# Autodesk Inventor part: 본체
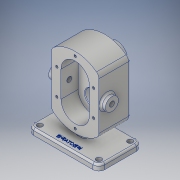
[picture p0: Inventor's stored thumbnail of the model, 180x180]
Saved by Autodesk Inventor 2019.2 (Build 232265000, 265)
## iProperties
Created: 2019-03
Part Number: 본체
Material: 알루미늄 6061
Document SubType Name: Modeling
Designer: User
Mass: 1187.16 g
Surface Area: 719.273 cm^2
Volume: 439.69 cm^3
Density: 2.7 g/cm^3
Appearance: 알루미늄 - 평지
Author: User
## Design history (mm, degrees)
sketch "스케치1"
  geometry: L1 (60, 73)-(-60, 73); L2 (-60, 73)-(-60, 0); L3 (-60, 0)-(60, 0); L4 (60, 0)-(60, 73); L5 (60, 73)-(-60, 0); L6 (-60, 73)-(60, 0); L7 (84, 0)-(-84, 0) reference; L8 (0, -14.6)-(0, 87.6) reference; 2 further points
  constraints: 12 end point, 3 midpoint, 2 parallel, 1 collinear, 1 horizontal, 1 perpendicular
  dimensions: "d0" = 73 distance between parallel lines of L3 L1; "d1" = 120 distance between parallel lines of L2 L4
extrude "돌출1" new body sketch "스케치1" distance "d2" = 10; taper "d3" = 0 deg
sketch "스케치2"
  geometry: L1 (0, -2)-(0, 12) reference; L2 (-40, 122.721)-(-40, 33.279); L3 (40, 122.721)-(40, 33.279); L4 (-40, 78)-(40, 78); L5 (-60, 0)-(60, 0) reference; L6 (-43.067, 138)-(65.49, 138); A1 r 60 centre (0, 78) between (40, 122.721) and (-40, 122.721); A2 r 60 centre (0, 78) between (-40, 33.279) and (40, 33.279); 1 further point
  constraints: 8 end point, 4 point on circle, 2 centre point, 2 midpoint, 2 point on line, 2 vertical, 1 horizontal, 1 tangent, 1 other
  dimensions: "d4" = 60 radius of A1; "d5" = 60 radius of A2; "d6" = 80 distance between parallel lines of L3 L2; "d7" = 78 distance between parallel lines of L5 L4; "d8" = 138 distance between parallel lines of L5 L6
extrude "돌출2" join sketch "스케치2" distance "d9" = 53; taper "d10" = 0 deg
sketch "스케치3"
  geometry: L1 (30, 43)-(0, 43); L2 (0, 43)-(0, 0); L3 (0, 0)-(30, 0); L4 (30, 0)-(30, 43); L5 (0, 0)-(10, 0) reference; L6 (0, 0)-(0, 73) reference
  constraints: 8 end point, 2 collinear, 2 parallel, 1 horizontal, 1 perpendicular
  dimensions: "d11" = 43 distance between parallel lines of L3 L1; "d12" = 30 distance between parallel lines of L6 L4
extrude "돌출3" join sketch "스케치3" stored distance "d13" = 12; taper "d14" = 0 deg
sketch "스케치4"
  geometry: L1 (-73, -33.279)-(0, -33.279) reference; L2 (-53, 0)-(-53, 89.443) reference; C1 r 11 at (-39, 44.721)
  constraints: 1 centre point
  dimensions: "d15" = 22 diameter of C1; "d16" = 78 distance from line of L1 C1.centre; "d17" = 14 distance from line of L2 C1.centre
extrude "돌출4" join sketch "스케치4" distance "d18" = 8; taper "d19" = 0 deg
fillet "모깎기1" dims "d20" = 3
sketch "스케치5"
  geometry: L1 (0, 56)-(0, 100); L2 (24, 56)-(24, 100); L3 (-24, 100)-(-24, 56); L4 (-60, 0)-(60, 0) reference; L5 (0, -27.6)-(0, 165.6) reference; A1 r 24 centre (0, 56) between (-24, 56) and (24, 56); A2 r 24 centre (0, 100) between (24, 100) and (-24, 100); 2 further points
  constraints: 8 end point, 4 point on circle, 4 tangent, 2 centre point, 1 collinear, 1 midpoint, 1 parallel, 1 vertical
  dimensions: "d21" = 24 radius of A2; "d22" = 44 distance of L1.start L1.end; "d23" = 78 distance from line of L4 point (0, 78)
extrude "돌출5" cut sketch "스케치5" distance "d24" = 29; taper "d25" = 0 deg
sketch "스케치6"
  geometry: C1 r 11 at (0, 0) reference; 2 further points
  constraints: 1 coincident
hole "구멍1" sketch "스케치6" at (0, 0) diameter "d26" = 8.376; stored, may be unused: countersink angle "d30" = 90 deg, drill point angle "d32" = 0 deg; dims "d27" = 20, "d28" = 4, "d29" = 2, "d31" = 8
fillet "모깎기2" dims "d33" = 3
sketch "스케치7"
  geometry: C1 r 11 at (0, 0) reference; 2 further points
  constraints: 1 coincident
hole "구멍2" sketch "스케치7" at (0, 0) diameter "d34" = 8.376; stored, may be unused: countersink angle "d38" = 90 deg, drill point angle "d40" = 0 deg; dims "d35" = 20, "d36" = 4, "d37" = 2, "d39" = 8
sketch "스케치8"
  geometry: C1 r 19 at (60, 100); A1 r 24 centre (60, 100) between (84, 100) and (36, 100) reference; 1 further point
  constraints: 1 centre point, 1 concentric
  dimensions: "d41" = 38 diameter of C1
extrude "돌출6" join sketch "스케치8" distance "d42" = 17; taper "d43" = 0 deg
sketch "스케치9"
  geometry: C1 r 14 at (0, 0); C2 r 19 at (0, 0) reference; 1 further point
  constraints: 1 centre point, 1 concentric
  dimensions: "d44" = 28 diameter of C1
extrude "돌출7" cut sketch "스케치9" distance "d45" = 7.3; taper "d46" = 0 deg
chamfer "모따기1" distance "d47" = 0.7; stored, may be unused: second distance "d48" = 2, angle "d49" = 30 deg
fillet "모깎기3" dims "d50" = 0.5
sketch "스케치10"
  geometry: A1 r 24 centre (0, 100) between (24, 100) and (-24, 100) reference; 2 further points
  constraints: 1 coincident
hole "구멍3" sketch "스케치10" at (0, 100) diameter "d51" = 17; stored, may be unused: countersink angle "d55" = 90 deg, drill point angle "d57" = 0 deg; dims "d52" = 20, "d53" = 25, "d54" = 15, "d56" = 27.3
sketch "스케치11"
  geometry: A1 r 24 centre (0, 56) between (-24, 56) and (24, 56) reference; 2 further points
  constraints: 1 coincident
hole "구멍4" sketch "스케치11" at (0, 56) diameter "d58" = 25; stored, may be unused: countersink angle "d62" = 90 deg, drill point angle "d64" = 0 deg; dims "d59" = 20, "d60" = 25, "d61" = 15, "d63" = 15
sketch "스케치12"
  geometry: L1 (24, 100)-(24, 56) reference; L2 (-24, 56)-(-24, 100) reference; L3 (31, 100)-(31, 56); L4 (-31, 56)-(-31, 100); A1 r 24 centre (0, 100) between (24, 100) and (-24, 100) reference; A2 r 24 centre (0, 56) between (-24, 56) and (24, 56) reference; A3 r 31 centre (0, 100) between (31, 100) and (-31, 100); A4 r 31 centre (0, 56) between (-31, 56) and (31, 56); 7 further points
  constraints: 6 point on circle, 4 coincident, 4 end point, 2 centre point, 3 other
  dimensions: "d66" = 31 radius of A3
hole "구멍5" sketch "스케치12" at (0, 131), (-31, 100), (31, 100), (31, 56), (-31, 56), (0, 25) diameter "d67" = 4.134; stored, may be unused: countersink angle "d71" = 90 deg, drill point angle "d73" = 118 deg; dims "d68" = 10, "d69" = 25, "d70" = 15, "d72" = 12
fillet "모깎기4" dims "d74" = 10
fillet "모깎기5" dims "d75" = 10
fillet "모깎기6" dims "d76" = 3
fillet "모깎기7" dims "d77" = 3
fillet "모깎기8" dims "d78" = 3
fillet "모깎기9" dims "d79" = 3
chamfer "모따기2" distance "d80" = 1; stored, may be unused: second distance "d81" = 2, angle "d82" = 45 deg
sketch "스케치13"
  geometry: A1 r 10 centre (-50, -63) between (-60, -63) and (-50, -73) reference; A2 r 10 centre (-50, -10) between (-50, 0) and (-60, -10) reference; A3 r 10 centre (50, -63) between (50, -73) and (60, -63) reference; A4 r 10 centre (50, -10) between (60, -10) and (50, 0) reference; 5 further points
  constraints: 4 coincident
hole "구멍6" sketch "스케치13" at (-50, -63), (-50, -10), (50, -63), (50, -10) diameter "d83" = 9; stored, may be unused: countersink angle "d87" = 90 deg, drill point angle "d89" = 118 deg; dims "d84" = 10, "d85" = 25, "d86" = 15, "d88" = 12
sketch "스케치14"
  geometry: L1 (-50, -73)-(50, -73) reference; L2 (-60, -10)-(-60, -63) reference; L3 (1.801, -63)-(0, -63); L4 (0, -63)-(0, -65.166); 1 further point
  constraints: 4 end point, 1 horizontal, 1 perpendicular, 1 other
  dimensions: "d90" = 10 distance from line of L1 L3.end; "d91" = 60 distance from line of L2 L3.end
feature "엠보싱1" sketch "스케치14" dims "d0" = 73, "d1" = 120, "d10" = 0, "d92" = 0.5, "d93" = 0
node "솔리드1"
mirror "미러1"
